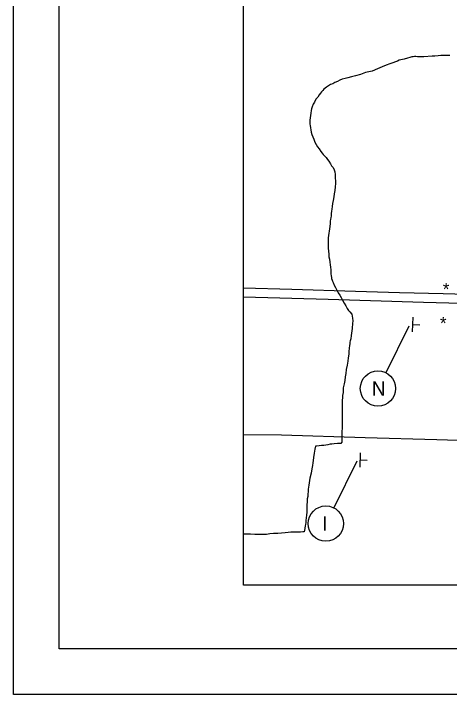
# Model space of a CAD drawing. Extents: x 1651.5 to 1685.5, y 1084.6 to 1106.6.
# Drawn here: x 1651.46 to 1656.25, y 1084.6 to 1092.09 of the extents above; entities that cross this region are included whole.
import ezdxf

# ---------------------------------------------------------------- set-up
doc = ezdxf.new("R2010")
doc.units = 0
for name, color, linetype in [('GM_X_County_Road', 7, 'Continuous'), ('GM_X_Minor_River', 7, 'Continuous'), ('GM_X_State_Route', 7, 'Continuous'), ('SC_Scratch1', 7, 'Continuous'), ('SH_Border', 7, 'Continuous'), ('SH_Data', 7, 'Continuous'), ('SH_Text', 7, 'Continuous'), ('SN_P_Signs', 7, 'Continuous')]:
    doc.layers.add(name, color=color, linetype=linetype)

msp = doc.modelspace()

# ---------------------------------------------------------------- linework, layer by layer
at = {"layer": 'GM_X_County_Road'}
msp.add_lwpolyline([(1653.9882, 1087.4595), (1654.4044, 1087.4528), (1655.323, 1087.4263), (1656.1102, 1087.4042), (1657.2691, 1087.3668), (1657.3069, 1087.3659), (1657.379, 1087.3642)], dxfattribs=at)
at = {"layer": 'GM_X_Minor_River'}
for points in [[(1656.2542, 1091.6271), (1656.2301, 1091.6272), (1656.2061, 1091.6246), (1656.182, 1091.6247), (1656.1552, 1091.6247), (1656.1258, 1091.6222), (1656.091, 1091.6196), (1656.0589, 1091.617), (1655.9679, 1091.6093), (1655.9438, 1091.6094), (1655.9197, 1091.6094), (1655.901, 1091.6122), (1655.8823, 1091.6149), (1655.8662, 1091.6149), (1655.8502, 1091.6123), (1655.8368, 1091.6097), (1655.8154, 1091.6044), (1655.7886, 1091.5965), (1655.7538, 1091.5859), (1655.735, 1091.5806), (1655.7163, 1091.578), (1655.6976, 1091.5727), (1655.6788, 1091.5647), (1655.6574, 1091.5568), (1655.6279, 1091.5461), (1655.5958, 1091.5355), (1655.5556, 1091.5196), (1655.5101, 1091.501), (1655.4592, 1091.4798), (1655.4029, 1091.4532), (1655.328, 1091.4374), (1655.2717, 1091.4162), (1655.2182, 1091.403), (1655.1727, 1091.3924), (1655.1352, 1091.3818), (1655.1031, 1091.3739), (1655.0736, 1091.366), (1655.0468, 1091.3527), (1655.02, 1091.3394), (1654.9906, 1091.3288), (1654.9692, 1091.3155), (1654.9451, 1091.3049)], [(1654.9451, 1091.3049), (1654.9236, 1091.2915), (1654.8995, 1091.2782), (1654.8834, 1091.2649), (1654.87, 1091.2543), (1654.8593, 1091.2409), (1654.8459, 1091.2276), (1654.8325, 1091.2116), (1654.819, 1091.1929), (1654.8029, 1091.1689), (1654.7841, 1091.1448), (1654.768, 1091.1128), (1654.7519, 1091.0888), (1654.7411, 1091.062), (1654.7357, 1091.0406), (1654.733, 1091.0219), (1654.7276, 1090.9898), (1654.7167, 1090.915), (1654.7167, 1090.8936), (1654.7166, 1090.8721), (1654.7193, 1090.8561), (1654.7245, 1090.8293), (1654.7272, 1090.8079), (1654.7325, 1090.7838), (1654.7404, 1090.757), (1654.7511, 1090.7302), (1654.7617, 1090.7061), (1654.7723, 1090.674), (1654.7857, 1090.6472), (1654.8017, 1090.6204), (1654.8177, 1090.5989), (1654.839, 1090.5694), (1654.8524, 1090.5533), (1654.863, 1090.5372), (1654.879, 1090.5211), (1654.8951, 1090.5051), (1654.9111, 1090.4836), (1654.9271, 1090.4621), (1654.9431, 1090.4353), (1654.9564, 1090.4139), (1654.9724, 1090.3924), (1654.983, 1090.3683), (1654.991, 1090.3469), (1654.9936, 1090.3175), (1654.9963, 1090.2987), (1654.9962, 1090.2719), (1654.9988, 1090.2505), (1654.9987, 1090.2184), (1654.996, 1090.181), (1654.9905, 1090.1409), (1654.9851, 1090.1061), (1654.9797, 1090.0713), (1654.9716, 1090.0313), (1654.9661, 1089.9965), (1654.9607, 1089.9644), (1654.958, 1089.9376), (1654.9553, 1089.9136), (1654.9525, 1089.8868), (1654.9498, 1089.8627), (1654.9471, 1089.8414), (1654.9443, 1089.8253), (1654.9416, 1089.8039), (1654.9389, 1089.7772), (1654.9361, 1089.7451), (1654.9198, 1089.6194), (1654.917, 1089.5873), (1654.917, 1089.5632), (1654.9169, 1089.5365), (1654.9195, 1089.507), (1654.9221, 1089.4749), (1654.9247, 1089.4428), (1654.9273, 1089.4107), (1654.9326, 1089.3866), (1654.9379, 1089.3545), (1654.9405, 1089.325), (1654.9431, 1089.2983), (1654.9457, 1089.2688), (1654.9457, 1089.2474), (1654.9483, 1089.2233), (1654.9509, 1089.2046), (1654.9536, 1089.1859), (1654.9562, 1089.1725), (1654.9615, 1089.1564), (1654.9669, 1089.143), (1654.9749, 1089.1296), (1654.9855, 1089.1001), (1654.9988, 1089.0733), (1655.0121, 1089.0439), (1655.0281, 1089.0144), (1655.0468, 1088.9902), (1655.0601, 1088.9635), (1655.0761, 1088.934), (1655.0921, 1088.9018), (1655.1107, 1088.8723), (1655.1267, 1088.8428), (1655.1427, 1088.8214), (1655.1561, 1088.8053), (1655.1774, 1088.7811), (1655.1853, 1088.7383), (1655.1879, 1088.7062), (1655.1852, 1088.6795)], [(1655.1852, 1088.6795), (1655.1852, 1088.6607), (1655.1825, 1088.6447), (1655.1824, 1088.6233), (1655.1797, 1088.5965), (1655.1743, 1088.5725), (1655.1715, 1088.5457), (1655.1661, 1088.511), (1655.1607, 1088.4869), (1655.158, 1088.4735), (1655.1553, 1088.4548), (1655.1526, 1088.4361), (1655.1498, 1088.4093), (1655.147, 1088.3692), (1655.1443, 1088.3398), (1655.1389, 1088.3024), (1655.1334, 1088.2649), (1655.1253, 1088.2195), (1655.1171, 1088.1713), (1655.1117, 1088.1285), (1655.1063, 1088.0911), (1655.1008, 1088.0537), (1655.0927, 1088.0136), (1655.0846, 1087.9708), (1655.0818, 1087.92), (1655.0764, 1087.8879), (1655.0763, 1087.8611), (1655.0736, 1087.837), (1655.0735, 1087.8103), (1655.0735, 1087.7889), (1655.0734, 1087.7675), (1655.0734, 1087.7434), (1655.0733, 1087.7113), (1655.0732, 1087.6792), (1655.0731, 1087.6444), (1655.0731, 1087.6123), (1655.0703, 1087.5695), (1655.0702, 1087.5427), (1655.0702, 1087.5214), (1655.0675, 1087.5), (1655.0674, 1087.4812), (1655.0674, 1087.4545), (1655.0673, 1087.4331), (1655.0673, 1087.4117), (1655.0672, 1087.3929), (1655.0672, 1087.3742), (1655.0591, 1087.3609), (1655.0457, 1087.3609), (1655.019, 1087.3583), (1654.9842, 1087.3557), (1654.9574, 1087.3532), (1654.9387, 1087.3505), (1654.9146, 1087.3453), (1654.8932, 1087.3427), (1654.8691, 1087.3374), (1654.845, 1087.3375), (1654.8182, 1087.3349), (1654.7915, 1087.3296), (1654.7781, 1087.3297), (1654.77, 1087.2976), (1654.7645, 1087.2521), (1654.7564, 1087.2066), (1654.7536, 1087.1719), (1654.7482, 1087.1478), (1654.7455, 1087.1184), (1654.7401, 1087.081), (1654.7319, 1087.0328), (1654.7184, 1086.9767), (1654.7049, 1086.9018), (1654.6994, 1086.8563), (1654.6967, 1086.8269), (1654.6966, 1086.8055), (1654.6939, 1086.7761), (1654.6885, 1086.7494), (1654.6884, 1086.7173), (1654.6856, 1086.6852), (1654.6856, 1086.6584), (1654.6828, 1086.6317), (1654.6828, 1086.6049), (1654.68, 1086.5728), (1654.6773, 1086.5407), (1654.6745, 1086.5113), (1654.6718, 1086.4899), (1654.6691, 1086.4685), (1654.6664, 1086.4525), (1654.6582, 1086.4017), (1654.6555, 1086.3883), (1654.6395, 1086.3883), (1654.6127, 1086.3857), (1654.5806, 1086.3859), (1654.5431, 1086.386), (1654.5083, 1086.3834), (1654.4789, 1086.3808), (1654.4441, 1086.3783), (1654.4066, 1086.373), (1654.3665, 1086.3705), (1654.3183, 1086.3679), (1654.2782, 1086.3654), (1654.2407, 1086.3602), (1654.2006, 1086.3603), (1654.1605, 1086.3577)], [(1654.1605, 1086.3577), (1654.1123, 1086.3579), (1654.0668, 1086.3607), (1654.0213, 1086.3609), (1653.9882, 1086.3629)]]:
    msp.add_lwpolyline(points, dxfattribs=at)
at = {"layer": 'GM_X_State_Route'}
for points in [[(1653.9882, 1089.0716), (1654.5206, 1089.0563), (1655.2182, 1089.0358), (1655.7006, 1089.0196), (1656.1829, 1089.0075), (1657.0775, 1088.9829), (1657.4657, 1088.9713), (1658.3454, 1088.9451), (1660.4221, 1088.8844), (1661.0999, 1088.8659), (1661.6244, 1088.8494), (1662.2585, 1088.8312), (1663.3078, 1088.8007), (1664.1166, 1088.777), (1664.5833, 1088.7638), (1664.6413, 1088.7624), (1665.4938, 1088.737), (1665.9748, 1088.7239), (1666.6305, 1088.7038), (1667.0677, 1088.6901), (1668.268, 1088.6514), (1668.4116, 1088.6492), (1668.6882, 1088.6439)], [(1653.9882, 1088.972), (1654.9177, 1088.9448), (1655.9668, 1088.9137), (1656.6661, 1088.8935), (1657.4608, 1088.8688), (1658.0564, 1088.8506), (1658.4943, 1088.8393), (1659.3219, 1088.8187), (1660.1311, 1088.7948), (1661.7276, 1088.748), (1662.3619, 1088.7295), (1662.8212, 1088.7178), (1663.9585, 1088.6833), (1664.5805, 1088.6652), (1665.2488, 1088.6454), (1666.6484, 1088.6041), (1667.6764, 1088.5732), (1668.5696, 1088.5488), (1668.6882, 1088.5445)]]:
    msp.add_lwpolyline(points, dxfattribs=at)
at = {"layer": 'SC_Scratch1'}
msp.add_lwpolyline([(1651.4632, 1106.6005), (1685.4632, 1106.6005), (1685.4632, 1084.6005), (1651.4632, 1084.6005)], close=True, dxfattribs=at)
at = {"layer": 'SH_Border'}
msp.add_lwpolyline([(1651.9632, 1106.1005), (1684.9632, 1106.1005), (1684.9632, 1085.1005), (1651.9632, 1085.1005)], close=True, dxfattribs=at)
at = {"layer": 'SH_Data'}
msp.add_lwpolyline([(1653.9882, 1105.4005), (1668.6882, 1105.4005), (1668.6882, 1085.8005), (1653.9882, 1085.8005)], close=True, dxfattribs=at)
at = {"layer": 'SH_Text'}
for p, q in [((1655.8057, 1088.6506), (1655.5525, 1088.1367)), ((1655.2333, 1087.1653), (1654.9801, 1086.6514))]:
    msp.add_line(p, q, dxfattribs=at)
for centre in [(1655.4649, 1087.964), (1654.8926, 1086.4787)]:
    msp.add_circle(centre, 0.1936, dxfattribs=at)
at = {"layer": 'SN_P_Signs'}
for p, q in [((1655.8472, 1088.7472), (1655.8424, 1088.5872)), ((1655.8448, 1088.6672), (1655.9248, 1088.6648)), ((1655.2692, 1087.2578), (1655.2644, 1087.0979)), ((1655.2668, 1087.1779), (1655.3468, 1087.1755))]:
    msp.add_line(p, q, dxfattribs=at)

# ---------------------------------------------------------------- texts
at = {"layer": 'SH_Text'}
for s, height, p in [('*', 0.14, (1656.177, 1088.9855)), ('*', 0.14, (1656.1463, 1088.6119)), ('N', 0.156, (1655.398, 1087.886)), ('I', 0.156, (1654.852, 1086.4007))]:
    msp.add_text(s, height=height, dxfattribs=at).set_placement(p)

doc.saveas('drawing.dxf')
